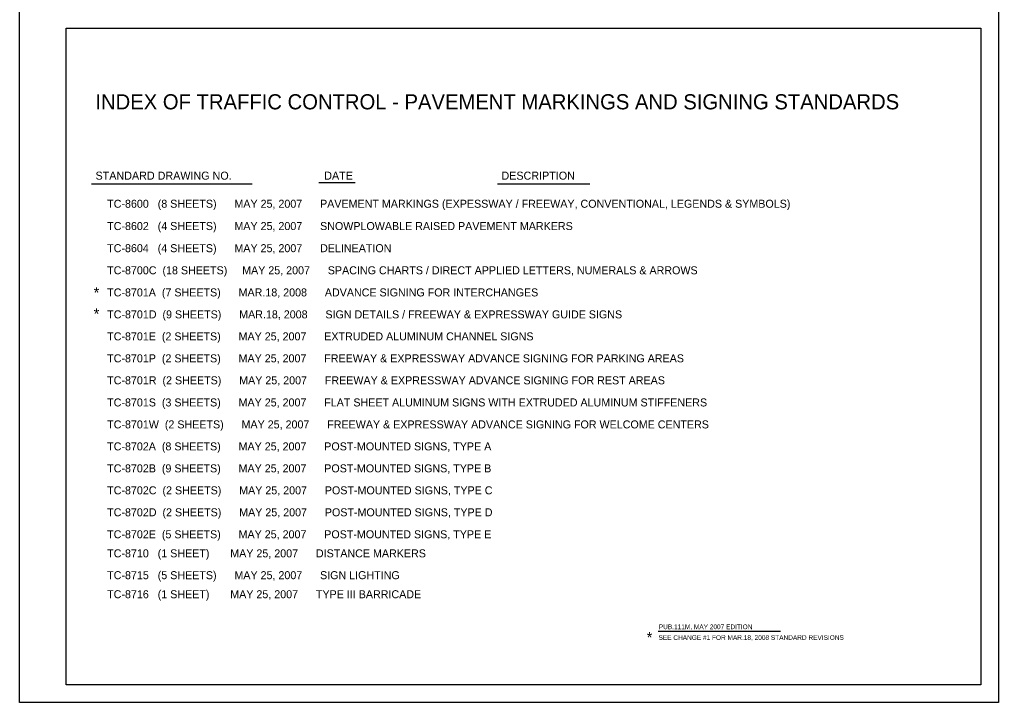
# Model space of a CAD drawing. Extents: x -1746 to -905, y 22 to 1210.
# Drawn here: x -1746 to -905, y 22 to 609 of the extents above; entities that cross this region are included whole.
import ezdxf

# ---------------------------------------------------------------- set-up
doc = ezdxf.new("R2010")
doc.units = 0
for name, color, linetype in [('1', 7, 'Continuous'), ('Level 1', 7, 'Continuous'), ('Level 2', 7, 'Continuous'), ('PLT-BNDY', 7, 'Continuous')]:
    doc.layers.add(name, color=color, linetype=linetype)

msp = doc.modelspace()

# ---------------------------------------------------------------- linework, layer by layer
at = {"layer": '1'}
msp.add_line((-1197.52, 83.48), (-1092.44, 83.48), dxfattribs=at)
at = {"layer": 'Level 1'}
for p, q in [((-1706.14, 601.17), (-920.14, 601.17)), ((-1706.14, 37.17), (-1706.14, 601.17)), ((-920.14, 601.17), (-920.14, 37.17)), ((-920.14, 37.17), (-1706.14, 37.17))]:
    msp.add_line(p, q, dxfattribs=at)
at = {"layer": 'Level 2'}
for p, q in [((-1684.39, 467.67), (-1546.27, 467.67)), ((-1488.89, 468.67), (-1457.77, 468.67)), ((-1335.52, 467.67), (-1256.14, 467.67)), ((-1670.89, 453.92), (-1670.89, 453.92)), ((-1670.89, 415.77), (-1670.89, 415.77)), ((-1670.89, 396.77), (-1670.89, 396.77)), ((-1670.89, 377.89), (-1670.89, 377.89)), ((-1670.89, 321.14), (-1670.89, 321.14)), ((-1670.89, 302.27), (-1670.89, 302.27)), ((-1670.89, 245.64), (-1670.89, 245.64)), ((-1670.89, 226.64), (-1670.89, 226.64)), ((-1670.89, 207.77), (-1670.89, 207.77)), ((-1670.89, 188.89), (-1670.89, 188.89)), ((-1670.89, 170.02), (-1670.89, 170.02)), ((-1670.89, 134.89), (-1670.89, 134.89))]:
    msp.add_line(p, q, dxfattribs=at)
at = {"layer": 'PLT-BNDY'}
msp.add_lwpolyline([(-1746.14, 616.17), (-905.14, 616.17), (-905.14, 22.17), (-1746.14, 22.17)], close=True, dxfattribs=at)

# ---------------------------------------------------------------- texts
at = {"layer": '1'}
for p in [(-1682.48, 369.5), (-1207.3, 73.31)]:
    msp.add_text('*', height=9.32, rotation=360, dxfattribs=at).set_placement(p)
for s, height, p in [('*', 9.32, (-1682.48, 351.26)), ('PUB.111M, MAY 2007 EDITION', 4.044, (-1196.89, 85.08)), ('SEE CHANGE #1 FOR MAR.18, 2008 STANDARD REVISIONS', 4.044, (-1197.16, 75.85))]:
    msp.add_text(s, height=height, dxfattribs=at).set_placement(p)
at = {"layer": 'Level 2'}
for s, height, p in [('INDEX OF TRAFFIC CONTROL - PAVEMENT MARKINGS AND SIGNING STANDARDS', 13, (-1681.03, 531.56)), ('STANDARD DRAWING NO.', 6.9067, (-1680.89, 471.17)), ('DATE', 6.907, (-1484.39, 471.17)), ('DESCRIPTION', 6.9067, (-1332.14, 471.17)), ('TC-8600   (8 SHEETS)      MAY 25, 2007      PAVEMENT MARKINGS (EXPESSWAY / FREEWAY, CONVENTIONAL, LEGENDS & SYMBOLS)', 6.87525, (-1670.89, 447.05)), ('TC-8602   (4 SHEETS)      MAY 25, 2007      SNOWPLOWABLE RAISED PAVEMENT MARKERS', 6.8753, (-1670.89, 427.89)), ('TC-8604   (4 SHEETS)      MAY 25, 2007      DELINEATION', 6.8753, (-1670.89, 408.89)), ('TC-8700C  (18 SHEETS)     MAY 25, 2007      SPACING CHARTS / DIRECT APPLIED LETTERS, NUMERALS & ARROWS', 6.87525, (-1670.89, 389.89)), ('TC-8701A  (7 SHEETS)      MAR.18, 2008      ADVANCE SIGNING FOR INTERCHANGES', 6.8753, (-1670.89, 370.89)), ('TC-8701D  (9 SHEETS)      MAR.18, 2008      SIGN DETAILS / FREEWAY & EXPRESSWAY GUIDE SIGNS', 6.8753, (-1670.89, 352.02)), ('TC-8701E  (2 SHEETS)      MAY 25, 2007      EXTRUDED ALUMINUM CHANNEL SIGNS', 6.8753, (-1670.89, 333.14)), ('TC-8701P  (2 SHEETS)      MAY 25, 2007      FREEWAY & EXPRESSWAY ADVANCE SIGNING FOR PARKING AREAS', 6.8753, (-1670.89, 314.27)), ('TC-8701R  (2 SHEETS)      MAY 25, 2007      FREEWAY & EXPRESSWAY ADVANCE SIGNING FOR REST AREAS', 6.8753, (-1670.89, 295.39)), ('TC-8701S  (3 SHEETS)      MAY 25, 2007      FLAT SHEET ALUMINUM SIGNS WITH EXTRUDED ALUMINUM STIFFENERS', 6.87525, (-1670.89, 276.39)), ('TC-8701W  (2 SHEETS)      MAY 25, 2007      FREEWAY & EXPRESSWAY ADVANCE SIGNING FOR WELCOME CENTERS', 6.8753, (-1670.89, 257.52)), ('TC-8702A  (8 SHEETS)      MAY 25, 2007      POST-MOUNTED SIGNS, TYPE A', 6.8753, (-1670.89, 238.64)), ('TC-8702B  (9 SHEETS)      MAY 25, 2007      POST-MOUNTED SIGNS, TYPE B', 6.8753, (-1670.89, 219.77)), ('TC-8702C  (2 SHEETS)      MAY 25, 2007      POST-MOUNTED SIGNS, TYPE C', 6.8753, (-1670.89, 200.89)), ('TC-8702D  (2 SHEETS)      MAY 25, 2007      POST-MOUNTED SIGNS, TYPE D', 6.8753, (-1670.89, 182.02)), ('TC-8702E  (5 SHEETS)      MAY 25, 2007      POST-MOUNTED SIGNS, TYPE E', 6.8753, (-1670.89, 163.14)), ('TC-8710   (1 SHEET)       MAY 25, 2007      DISTANCE MARKERS', 6.8753, (-1670.89, 146.77)), ('TC-8715   (5 SHEETS)      MAY 25, 2007      SIGN LIGHTING', 6.8753, (-1670.89, 128.02)), ('TC-8716   (1 SHEET)       MAY 25, 2007      TYPE III BARRICADE', 6.8753, (-1670.89, 111.64))]:
    msp.add_text(s, height=height, dxfattribs=at).set_placement(p)

doc.saveas('drawing.dxf')
